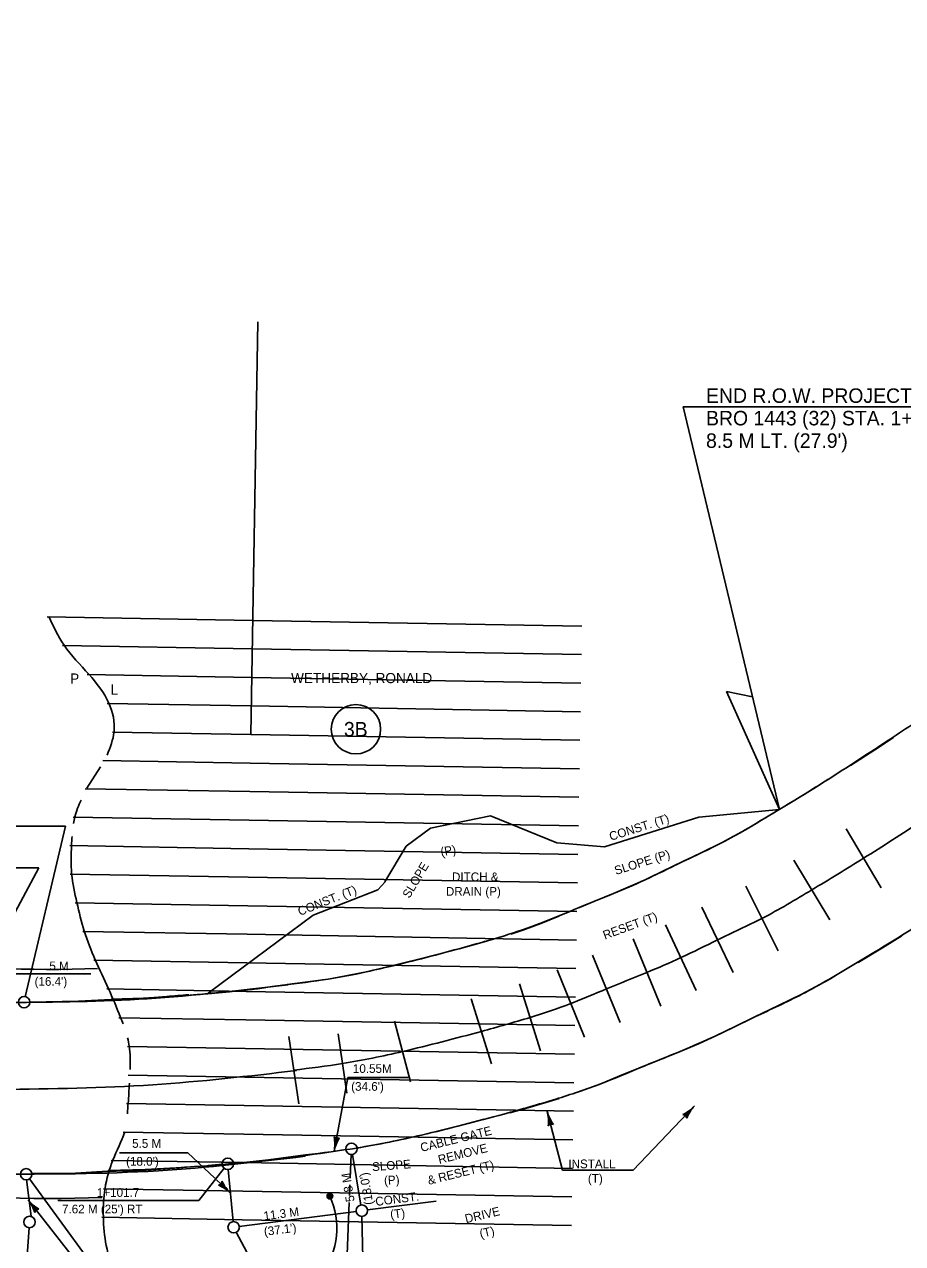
# Model space of a CAD drawing. Extents: x 435838 to 436160, y 121991 to 122158.
# Drawn here: x 436006.3 to 436083.1, y 122048.1 to 122154.8 of the extents above; entities that cross this region are included whole.
import ezdxf

# ---------------------------------------------------------------- set-up
doc = ezdxf.new("R2010")
doc.units = 0
for name, color, linetype in [('Level 1', 7, 'Continuous'), ('Level 10', 7, 'Continuous'), ('Level 12', 7, 'Continuous'), ('Level 16', 7, 'Continuous'), ('Level 2', 7, 'Continuous'), ('Level 3', 7, 'Continuous'), ('Level 30', 7, 'Continuous'), ('Level 37', 7, 'Continuous'), ('Level 38', 7, 'Continuous'), ('Level 4', 7, 'Continuous'), ('Level 5', 7, 'Continuous'), ('Level 57', 7, 'Continuous'), ('Level 62', 7, 'Continuous'), ('Level 7', 7, 'Continuous')]:
    doc.layers.add(name, color=color, linetype=linetype)

msp = doc.modelspace()

# ---------------------------------------------------------------- linework, layer by layer
at = {"layer": 'Level 1'}
msp.add_line((436035.525, 122056.465), (436035.392, 122056.446), dxfattribs=at)
for points in [[(436078.585, 122089.944), (436080.699, 122091.318), (436082.348, 122092.403)], [(436054.873, 122077.518), (436056.117, 122078.025), (436057.846, 122078.731), (436060.604, 122079.932), (436062.142, 122080.676), (436063.68, 122081.42), (436065.508, 122082.304), (436067.336, 122083.189), (436069.382, 122084.3), (436071.379, 122085.503), (436073.571, 122086.824), (436075.746, 122088.17), (436076.621, 122088.73)], [(436048.838, 122075.173), (436049.901, 122075.511), (436051.483, 122076.093), (436053.053, 122076.734)], [(436079.243, 122072.683), (436081.396, 122073.982), (436083.081, 122075.024)], [(436029.26, 122070.752), (436030.861, 122070.969), (436032.873, 122071.242), (436035.303, 122071.667), (436037.712, 122072.211), (436041.02, 122073.028), (436044.314, 122073.897), (436046.302, 122074.451), (436046.615, 122074.544)], [(436054.942, 122061.416), (436056.737, 122062.076), (436058.398, 122062.754), (436060.058, 122063.432), (436061.866, 122064.17), (436063.674, 122064.909), (436065.281, 122065.579), (436066.866, 122066.298), (436068.54, 122067.108), (436070.214, 122067.918), (436072.275, 122068.915), (436074.336, 122069.913), (436076.704, 122071.199), (436077.245, 122071.525)], [(436013.877, 122069.462), (436010.992, 122069.294), (436006.741, 122069.213)], [(436048.749, 122059.52), (436050.528, 122060.016), (436052.795, 122060.687), (436053.067, 122060.773)], [(436035.528, 122056.472), (436038.211, 122056.94), (436041.042, 122057.579), (436044.65, 122058.47), (436046.508, 122058.961)], [(436006.925, 122054.197), (436010.753, 122054.235), (436013.551, 122054.413)]]:
    msp.add_lwpolyline(points, dxfattribs=at)
for centre, radius, start, end in [((436008.511359, 122200.084174), 128, 263.87434448, 271.86219726), ((436010.786853, 122199.941299), 130.5, 271.35483333, 277.97162778), ((436010.751853, 122199.936299), 145.5, 271.11879444, 277.94544167), ((436008.286494, 122200.030697), 148, 264.45392496, 271.85649441)]:
    msp.add_arc(centre, radius, start, end, dxfattribs=at)
for points in [[(436028.85, 122070.697), (436032.873, 122071.242), (436037.712, 122072.211), (436044.314, 122073.897), (436048.282, 122075.037), (436051.469, 122076.128), (436054.388, 122077.32), (436057.846, 122078.731), (436060.604, 122079.932), (436063.68, 122081.42), (436067.336, 122083.189), (436071.379, 122085.503), (436075.746, 122088.17), (436080.678, 122091.35), (436085.033, 122094.249), (436090.18, 122097.927), (436094.134, 122100.887), (436098.234, 122104.061), (436100.934, 122106.23), (436103.533, 122108.318), (436106.685, 122111.192), (436109.967, 122114.237), (436112.189, 122116.336), (436114.874, 122119.011), (436117.223, 122121.352), (436119.16, 122123.281), (436121.551, 122125.723), (436124.108, 122128.36), (436126.322, 122130.636), (436128.824, 122133.185), (436131.511, 122135.996), (436133.694, 122138.283), (436135.881, 122140.633), (436138.377, 122143.324), (436140.557, 122145.686), (436142.871, 122148.165), (436145.11, 122150.508), (436147.344, 122152.824), (436149.292, 122154.844)], [(436030.864, 122055.833), (436035.355, 122056.442), (436041.042, 122057.579), (436048.242, 122059.419), (436052.784, 122060.723), (436056.737, 122062.076), (436060.058, 122063.432), (436063.674, 122064.909), (436066.866, 122066.298), (436070.214, 122067.918), (436074.336, 122069.913), (436079.015, 122072.591), (436083.72, 122075.464), (436088.9, 122078.804), (436093.551, 122081.901), (436099.036, 122085.819), (436103.22, 122088.951), (436107.524, 122092.283), (436110.328, 122094.536), (436113.293, 122096.918), (436116.839, 122100.152), (436120.219, 122103.287), (436122.635, 122105.57), (436125.46, 122108.385), (436127.809, 122110.724), (436129.812, 122112.719), (436132.295, 122115.255), (436134.868, 122117.91), (436137.05, 122120.152), (436139.598, 122122.749), (436142.357, 122125.634), (436144.61, 122127.995), (436146.871, 122130.423), (436149.387, 122133.138), (436151.551, 122135.482), (436153.775, 122137.865), (436155.93, 122140.118), (436158.142, 122142.412), (436160.09, 122144.432)], [(436027.254, 122070.465), (436027.222, 122070.46), (436025.862, 122070.304), (436022.092, 122069.958)], [(436020.653, 122069.862), (436018.729, 122069.713), (436015.817, 122069.509), (436013.875, 122069.462)], [(436034.403, 122056.301), (436029.984, 122055.657), (436029.463, 122055.584)], [(436020.449, 122054.768), (436019.836, 122054.721), (436016.525, 122054.489), (436013.563, 122054.417)], [(436023.574, 122055.025), (436022.386, 122054.919), (436022.367, 122054.917)], [(436027.411, 122055.35), (436027.395, 122055.348), (436024.571, 122055.105)]]:
    msp.add_spline(points, degree=3, dxfattribs=at)
at = {"layer": 'Level 10'}
for p, q in [((436100.52, 122121.357), (436063.934, 122121.357)), ((436063.934, 122121.357), (436072.355, 122086.091)), ((436067.726, 122096.417), (436070.002, 122095.944)), ((436072.355, 122086.091), (436067.726, 122096.417)), ((436037.834, 122079.766), (436039.691, 122082.888)), ((436031.543, 122076.828), (436037.194, 122079.061)), ((436037.194, 122079.061), (436037.835, 122079.767))]:
    msp.add_line(p, q, dxfattribs=at)
at = {"layer": 'Level 12'}
for p, q in [((436078.191, 122084.396), (436081.274, 122079.238)), ((436073.629, 122081.665), (436076.765, 122076.428)), ((436069.43, 122079.387), (436072.241, 122073.714)), ((436065.569, 122077.52), (436068.325, 122071.818)), ((436062.397, 122075.986), (436065.072, 122070.243)), ((436059.547, 122074.774), (436061.972, 122068.865)), ((436056.013, 122073.323), (436058.432, 122067.428)), ((436052.895, 122072.043), (436055.31, 122066.161)), ((436049.607, 122070.815), (436051.459, 122064.944)), ((436045.39, 122069.497), (436047.165, 122063.818)), ((436038.673, 122067.553), (436040.08, 122062.236)), ((436029.421, 122066.204), (436030.292, 122060.325)), ((436033.73, 122066.434), (436034.498, 122061.249))]:
    msp.add_line(p, q, dxfattribs=at)
for points in [[(436029.857, 122063.265), (436034.114, 122063.842), (436039.377, 122064.895), (436046.278, 122066.658), (436050.533, 122067.88), (436054.103, 122069.102), (436057.223, 122070.376), (436060.76, 122071.82), (436063.735, 122073.115), (436066.947, 122074.669), (436070.836, 122076.551), (436075.197, 122079.047), (436079.733, 122081.817), (436084.789, 122085.077), (436089.292, 122088.075), (436094.608, 122091.873), (436098.677, 122094.919), (436102.879, 122098.172), (436105.631, 122100.383), (436108.413, 122102.618), (436111.762, 122105.672), (436115.093, 122108.762), (436117.412, 122110.953), (436120.167, 122113.698), (436122.516, 122116.038), (436124.486, 122118), (436126.923, 122120.489), (436129.488, 122123.135), (436131.686, 122125.394), (436134.211, 122127.967), (436136.934, 122130.815), (436139.152, 122133.139), (436141.376, 122135.528), (436143.882, 122138.231), (436146.054, 122140.584), (436148.323, 122143.015), (436150.52, 122145.313), (436152.743, 122147.618), (436154.691, 122149.638)], [(436004.196, 122061.568), (436017.518, 122061.982), (436030.094, 122063.223)]]:
    msp.add_spline(points, degree=3, dxfattribs=at)
at = {"layer": 'Level 16'}
for p, q in [((436052.19, 122058.533), (436052.221, 122058.741)), ((436052.445, 122058.599), (436052.317, 122058.766)), ((436063.912, 122059.375), (436064.145, 122059.289)), ((436064.061, 122059.392), (436064.252, 122059.478)), ((436064.249, 122059.063), (436064.144, 122059.29)), ((436064.254, 122059.213), (436064.325, 122059.411)), ((436052.123, 122058.398), (436052.322, 122058.548)), ((436052.568, 122058.514), (436052.321, 122058.548)), ((436033.382, 122057.409), (436033.591, 122057.274)), ((436033.458, 122057.279), (436033.504, 122057.074)), ((436033.834, 122057.326), (436033.59, 122057.274)), ((436033.717, 122057.232), (436033.601, 122057.056)), ((436023.252, 122053.187), (436023.479, 122053.289)), ((436023.568, 122053.521), (436023.479, 122053.289)), ((436023.583, 122053.372), (436023.667, 122053.179)), ((436023.402, 122053.181), (436023.6, 122053.108)), ((436007.188, 122050.948), (436007.133, 122051.151)), ((436007.395, 122051.11), (436007.211, 122051.211)), ((436007.181, 122050.797), (436007.303, 122051.014)), ((436007.542, 122051.081), (436007.302, 122051.014))]:
    msp.add_line(p, q, dxfattribs=at)
for centre, start, end in [((436055.346079, 122060.509996), 194.5443612, 215.76761397), ((436048.725303, 122058.79066), 353.34731956, 14.57057233), ((436062.410474, 122062.44913), 295.96117883, 317.18443161), ((436067.427139, 122057.798982), 137.15822058, 158.38147336), ((436030.021495, 122056.770438), 349.60175162, 10.8250044), ((436036.749818, 122055.537363), 148.40470995, 169.62796273), ((436026.655382, 122054.993781), 205.42778553, 226.65103831), ((436021.958734, 122050.020623), 46.6248272, 67.84807998), ((436009.293958, 122054.019012), 218.04373631, 239.26698909), ((436003.907845, 122049.802307), 16.84669465, 38.06994743)]:
    msp.add_arc(centre, 3.420733, start, end, dxfattribs=at)
at = {"layer": 'Level 2'}
for p, q in [((436034.98, 122055.884), (436035.724, 122051.45)), ((436024.119, 122054.563), (436024.539, 122049.998)), ((436006.873, 122050.465), (436006.452, 122053.692)), ((436025.081, 122049.564), (436035.311, 122050.893))]:
    msp.add_line(p, q, dxfattribs=at)
for points in [[(436029.353, 122070.73), (436017.03, 122069.514), (436004.948, 122069.18)], [(436003.492, 122054.162), (436018.006, 122054.45), (436030.835, 122055.716)]]:
    msp.add_spline(points, degree=3, dxfattribs=at)
at = {"layer": 'Level 3'}
for p, q in [((436012.926, 122089.825), (436011.747, 122087.962)), ((436021.539, 122051.841), (436023.764, 122054.668)), ((436035.964, 122044.208), (436035.819, 122050.457)), ((436028.482, 122042.218), (436024.821, 122049.059))]:
    msp.add_line(p, q, dxfattribs=at)
for centre, radius in [((436006.242384, 122069.212009), 0.4997), ((436034.897, 122056.377), 0.499685), ((436024.073, 122055.061), 0.5), ((436006.428628, 122054.141816), 0.4997), ((436035.807, 122050.957), 0.499685), ((436006.713, 122049.963), 0.4997), ((436024.585, 122049.5), 0.499685)]:
    msp.add_circle(centre, radius, dxfattribs=at)
for points in [[(436008.394, 122102.991), (436009.749, 122100.468), (436011.906, 122097.93), (436013.662, 122095.4), (436014.119, 122092.891), (436013.507, 122090.858)], [(436011.227, 122086.914), (436010.689, 122085.449), (436010.569, 122084.861)], [(436010.439, 122083.735), (436010.395, 122082.954), (436010.402, 122080.453), (436010.859, 122077.945), (436011.515, 122075.434), (436012.472, 122072.916), (436013.629, 122070.396), (436014.685, 122067.878), (436014.901, 122067.326)], [(436015.3, 122066.08), (436015.442, 122065.368), (436015.519, 122063.331)], [(436015.46, 122062.107), (436015.355, 122060.365), (436015.283, 122059.437)], [(436015.063, 122057.872), (436015.062, 122057.869), (436014.018, 122055.387), (436013.325, 122052.899), (436013.182, 122050.4), (436013.438, 122047.896), (436013.895, 122045.388), (436013.31, 122042.961), (436011.708, 122040.425), (436010.5, 122038.607)]]:
    msp.add_spline(points, degree=3, dxfattribs=at)
at = {"layer": 'Level 30'}
for p, q in [((436041.81, 122084.463), (436047.077, 122085.522)), ((436047.077, 122085.522), (436052.886, 122083.161)), ((436057.059, 122082.817), (436065.317, 122085.425)), ((436065.317, 122085.425), (436072.355, 122086.091)), ((436039.69, 122082.887), (436041.81, 122084.463)), ((436052.886, 122083.161), (436057.059, 122082.817)), ((436022.356, 122069.997), (436031.543, 122076.828)), ((436036.303, 122051.019), (436042.309, 122051.776))]:
    msp.add_line(p, q, dxfattribs=at)
at = {"layer": 'Level 37'}
for p, q in [((436008.255, 122102.964), (436008.255, 122102.964)), ((436009.61, 122100.441), (436009.61, 122100.441)), ((436011.767, 122097.903), (436011.767, 122097.903)), ((436013.523, 122095.373), (436013.523, 122095.373)), ((436013.98, 122092.864), (436013.98, 122092.864)), ((436013.137, 122090.378), (436013.137, 122090.378)), ((436011.593, 122087.905), (436011.593, 122087.905)), ((436010.55, 122085.422), (436010.55, 122085.422)), ((436010.256, 122082.927), (436010.256, 122082.927)), ((436010.263, 122080.426), (436010.263, 122080.426)), ((436010.72, 122077.918), (436010.72, 122077.918)), ((436011.376, 122075.407), (436011.376, 122075.407)), ((436012.333, 122072.889), (436012.333, 122072.889)), ((436013.49, 122070.369), (436013.49, 122070.369)), ((436014.546, 122067.851), (436014.546, 122067.851)), ((436015.303, 122065.337), (436015.303, 122065.337)), ((436015.359, 122062.836), (436015.359, 122062.836)), ((436015.216, 122060.338), (436015.216, 122060.338)), ((436014.923, 122057.842), (436014.923, 122057.842)), ((436013.879, 122055.36), (436013.879, 122055.36)), ((436013.186, 122052.872), (436013.186, 122052.872)), ((436013.043, 122050.373), (436013.043, 122050.373))]:
    msp.add_line(p, q, dxfattribs=at)
at = {"layer": 'Level 38'}
for p, q in [((436026.081, 122092.655), (436026.705, 122128.798)), ((436026.252, 122102.653), (436008.255, 122102.964)), ((436026.252, 122102.653), (436055.066, 122102.153)), ((436026.208, 122100.154), (436009.61, 122100.441)), ((436026.208, 122100.154), (436055.022, 122099.654)), ((436026.165, 122097.654), (436011.767, 122097.903)), ((436026.165, 122097.654), (436054.979, 122097.154)), ((436026.121, 122095.155), (436013.523, 122095.373)), ((436026.121, 122095.155), (436054.935, 122094.655)), ((436026.078, 122092.655), (436013.98, 122092.864)), ((436026.078, 122092.655), (436054.892, 122092.155)), ((436026.035, 122090.155), (436013.137, 122090.378)), ((436026.035, 122090.155), (436054.849, 122089.655)), ((436025.991, 122087.656), (436011.593, 122087.905)), ((436025.991, 122087.656), (436054.805, 122087.156)), ((436025.948, 122085.156), (436010.55, 122085.422)), ((436025.948, 122085.156), (436054.762, 122084.656)), ((436025.904, 122082.657), (436010.256, 122082.927)), ((436025.904, 122082.657), (436054.718, 122082.157)), ((436025.861, 122080.157), (436010.263, 122080.426)), ((436025.861, 122080.157), (436054.675, 122079.657)), ((436025.818, 122077.657), (436010.72, 122077.918)), ((436025.818, 122077.657), (436054.632, 122077.157)), ((436025.774, 122075.158), (436011.376, 122075.407)), ((436025.774, 122075.158), (436054.588, 122074.658)), ((436025.731, 122072.658), (436012.333, 122072.889)), ((436025.731, 122072.658), (436054.545, 122072.158)), ((436025.688, 122070.158), (436013.49, 122070.369)), ((436025.688, 122070.158), (436054.502, 122069.658)), ((436025.644, 122067.659), (436014.546, 122067.851)), ((436025.644, 122067.659), (436054.458, 122067.159)), ((436025.601, 122065.159), (436015.303, 122065.337)), ((436025.601, 122065.159), (436054.415, 122064.659)), ((436025.557, 122062.66), (436015.359, 122062.836)), ((436025.557, 122062.66), (436054.371, 122062.16)), ((436025.514, 122060.16), (436015.216, 122060.338)), ((436025.514, 122060.16), (436054.328, 122059.66)), ((436025.471, 122057.66), (436014.923, 122057.842)), ((436025.471, 122057.66), (436054.285, 122057.16)), ((436025.427, 122055.161), (436013.879, 122055.36)), ((436025.427, 122055.161), (436054.241, 122054.661)), ((436025.384, 122052.661), (436013.186, 122052.872)), ((436025.384, 122052.661), (436054.198, 122052.161)), ((436025.341, 122050.161), (436013.043, 122050.373)), ((436025.341, 122050.161), (436054.155, 122049.661))]:
    msp.add_line(p, q, dxfattribs=at)
at = {"layer": 'Level 5'}
for p, q in [((435996.502, 122084.642), (436009.873, 122084.642)), ((436009.873, 122084.642), (436006.323, 122069.693)), ((435993.538, 122080.982), (436007.53, 122080.982)), ((436007.53, 122080.982), (436003.557, 122073.553)), ((436034.877, 122055.878), (436034.794, 122053.809)), ((436011.899, 122046.629), (436006.723, 122053.738)), ((436034.77, 122053.218), (436034.732, 122052.27)), ((436021.539, 122051.841), (436009.189, 122051.841)), ((436034.707, 122051.664), (436034.194, 122038.922)), ((436006.471, 122046.633), (436006.677, 122049.465))]:
    msp.add_line(p, q, dxfattribs=at)
for centre, radius in [((436035.292, 122093.117), 2.16), ((436033.013018, 122052.229095), 0.248182), ((436033.013111, 122052.226146), 0.198545), ((436033.013186, 122052.223786), 0.158836), ((436033.013246, 122052.221898), 0.127069), ((436033.013293, 122052.220388), 0.101655), ((436033.013362, 122052.218214), 0.065059)]:
    msp.add_circle(centre, radius, dxfattribs=at)
msp.add_arc((436026.777595, 122049.417149), 6.836392, 324.64157466, 24.20419966, dxfattribs=at)
at = {"layer": 'Level 57'}
msp.add_line((436052.885, 122083.161), (436052.886, 122083.161), dxfattribs=at)
at = {"layer": 'Level 62'}
msp.add_line((436013.081, 122052.106), (436013.081, 122052.106), dxfattribs=at)
at = {"layer": 'Level 7'}
for p, q in [((436004.429, 122071.703), (436012.078, 122071.703)), ((436034.571, 122062.619), (436033.386, 122056.153)), ((436039.872, 122062.619), (436034.571, 122062.619)), ((436053.359, 122054.497), (436052.035, 122059.651)), ((436059.562, 122054.497), (436064.919, 122060.125)), ((436014.586, 122056.023), (436020.585, 122056.023)), ((436020.585, 122056.023), (436022.942, 122053.797)), ((436053.359, 122054.497), (436059.562, 122054.497)), ((436023.097, 122053.65), (436024.308, 122052.507)), ((436012.647, 122044.187), (436006.6, 122051.911))]:
    msp.add_line(p, q, dxfattribs=at)

# ---------------------------------------------------------------- texts
at = {"layer": 'Level 10'}
for s, p in [('END R.O.W. PROJECT', (436065.939, 122121.697)), ('BRO 1443 (32) STA. 1+1157.4', (436065.939, 122119.727)), ("8.5 M LT. (27.9')", (436065.939, 122117.757))]:
    msp.add_text(s, height=1.270002, dxfattribs=at).set_placement(p)
at = {"layer": 'Level 3'}
for s, p in [('P', (436010.273, 122097.109)), ('L', (436013.803, 122096.146))]:
    msp.add_text(s, height=0.889002, dxfattribs=at).set_placement(p)
at = {"layer": 'Level 4'}
msp.add_text('WETHERBY, RONALD', height=0.889002, dxfattribs=at).set_placement((436029.614, 122097.154))
at = {"layer": 'Level 5'}
for s, height, p in [('3B', 1.270002, (436034.242, 122092.482)), ('1+101.7', 0.761874, (436012.613, 122052.166)), ("7.62 M (25') RT", 0.761874, (436009.562, 122050.719))]:
    msp.add_text(s, height=height, dxfattribs=at).set_placement(p)
at = {"layer": 'Level 7'}
for s, height, rotation, p in [('CONST. (T)', 0.761874, 17.5268966, (436057.604, 122083.339)), ('(P)', 0.761868, 10.5003203, (436042.77, 122081.99)), ('SLOPE (P)', 0.761874, 17.5268966, (436058.054, 122080.348)), ('SLOPE', 0.761874, 59.25578476, (436039.968, 122078.251)), ('CONST. (T)', 0.761838, 21.63450288, (436030.386, 122076.763)), ('RESET (T)', 0.761994, 20.25176788, (436057.082, 122074.69)), ('CABLE GATE', 0.762, 13.90037977, (436041.031, 122056.093)), ('REMOVE ', 0.762, 13.90037977, (436042.587, 122055.047)), ('SLOPE', 0.761874, 4.39812233, (436036.731, 122054.411)), ('& RESET (T)', 0.762, 13.90037977, (436041.672, 122053.212)), ('5.8 M', 0.762, 99.52517407, (436035.182, 122051.79)), ("(18.0')", 0.762, 99.52517407, (436036.81, 122051.528)), ('(P)', 0.761874, 4.39812233, (436037.778, 122053.212)), ('CONST.', 0.761874, 7.18371503, (436037.042, 122051.367)), ('11.3 M', 0.761874, 7.40195518, (436027.259, 122050.111)), ('(T)', 0.761874, 7.18371503, (436038.336, 122050.245)), ('DRIVE', 0.761868, 13.28357582, (436044.931, 122049.857)), ("(37.1')", 0.761874, 7.40195518, (436027.289, 122048.742)), ('(T)', 0.761868, 13.28357582, (436046.214, 122048.556))]:
    msp.add_text(s, height=height, rotation=rotation, dxfattribs=at).set_placement(p)
for s, height, p in [('DITCH &', 0.761874, (436043.701, 122079.81)), ('DRAIN (P)', 0.761874, (436043.166, 122078.534)), ('5 M', 0.761874, (436008.452, 122072.012)), ("(16.4')", 0.761874, (436007.162, 122070.651)), ('10.55M', 0.762, (436035.022, 122063.019)), ("(34.6')", 0.762, (436034.875, 122061.457)), ('5.5 M', 0.762, (436015.698, 122056.458)), ("(18.0')", 0.762, (436015.17, 122054.896)), ('INSTALL', 0.761874, (436053.885, 122054.672)), ('(T)', 0.761874, (436055.598, 122053.396))]:
    msp.add_text(s, height=height, dxfattribs=at).set_placement(p)

doc.saveas('drawing.dxf')
